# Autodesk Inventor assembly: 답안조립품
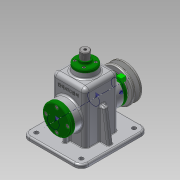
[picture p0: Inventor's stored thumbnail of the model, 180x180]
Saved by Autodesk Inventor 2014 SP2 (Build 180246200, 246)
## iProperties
Created: 2016-08
Part Number: 답안조립품
Document SubType Name: Assembly
Designer: user
Author: user
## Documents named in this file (19)
- C:\Users\user\Desktop\460820V1013\답안조립품.iam
- C:\Users\user\Desktop\460820V1013\본체.ipt
- C:\Users\user\Desktop\460820V1013\뒤커버.ipt
- C:\Users\user\Desktop\460820V1013\앞커버.ipt
- C:\Users\user\Desktop\460820V1013\베어링 15 x 35 x 11.ipt
- C:\Users\user\Desktop\460820V1013\편심축.ipt
- C:\Users\user\Desktop\460820V1013\V-벨트풀리.ipt
- C:\Users\user\Desktop\460820V1013\키 5 x 5 x 14.ipt
- C:\Users\user\Desktop\460820V1013\볼트 M6 x 12.ipt
- C:\Users\user\Desktop\460820V1013\와셔.ipt
- C:\Users\user\Desktop\460820V1013\멈춤링 6 x 5.ipt
- C:\Users\user\Desktop\460820V1013\멈춤링 15 x 1.ipt
- C:\Users\user\Desktop\460820V1013\오일실 15 25 7.ipt
- C:\Users\user\Desktop\460820V1013\링크.ipt
- C:\Users\user\Desktop\460820V1013\슬라이드바.ipt
- C:\Users\user\Desktop\460820V1013\고정핀.ipt
- C:\Users\user\Desktop\460820V1013\상부부시.ipt
- C:\Users\user\Desktop\460820V1013\볼트 M4 x 10.ipt
- C:\Users\user\Desktop\460820V1013\볼트 M3 x 8.ipt
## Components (15 placed, 5 different names)
1. V-벨트풀리:1 — 각도:1
2. ISO 4018 M6 x 12:1 — 강체:1
3. 고정핀:1
4. ISO 4762 M4 x 10:1 — 강체:4
5. ISO 4762 M4 x 10:3
6. ISO 4762 M4 x 10:4
7. ISO 4762 M4 x 10:5
8. ISO 4762 M4 x 10:2 — 강체:5
9. ISO 4762 M4 x 10:6
10. ISO 4762 M4 x 10:7
11. ISO 4762 M4 x 10:8
12. ISO 4762 M3 x 8:1 — 강체:6
13. ISO 4762 M3 x 8:2
14. ISO 4762 M3 x 8:3
15. ISO 4762 M3 x 8:4
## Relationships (5: WeldJoint 4, Angle 1)
- 각도:1 [Angle]: V-벨트풀리:1
- 강체:1 [WeldJoint]: ISO 4018 M6 x 12:1
- 강체:4 [WeldJoint]: ISO 4762 M4 x 10:1
- 강체:5 [WeldJoint]: ISO 4762 M4 x 10:2
- 강체:6 [WeldJoint]: ISO 4762 M3 x 8:1
